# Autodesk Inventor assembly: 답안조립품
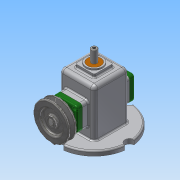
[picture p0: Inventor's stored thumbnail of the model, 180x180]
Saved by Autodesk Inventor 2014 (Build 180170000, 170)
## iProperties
Created: 2018-07
Part Number: 답안조립품
Document SubType Name: Assembly
Designer: user
Author: user
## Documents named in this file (14)
- C:\Users\user\Desktop\480707V1005\답안조립품.iam
- C:\Users\user\Desktop\480707V1005\본체.ipt
- C:\Users\user\Desktop\480707V1005\앞커버.ipt
- C:\Users\user\Desktop\480707V1005\뒤커버.ipt
- C:\Users\user\Desktop\480707V1005\베어링 12x32x10.ipt
- C:\Users\user\Desktop\480707V1005\오일 실 12 25 7.ipt
- C:\Users\user\Desktop\480707V1005\편심축.ipt
- C:\Users\user\Desktop\480707V1005\V벨트풀리.ipt
- C:\Users\user\Desktop\480707V1005\링크.ipt
- C:\Users\user\Desktop\480707V1005\슬라이드.ipt
- C:\Users\user\Desktop\480707V1005\부시.ipt
- C:\Users\user\Desktop\480707V1005\핀 5x18.ipt
- C:\Users\user\Desktop\480707V1005\고정핀 1.2x8.ipt
- C:\Users\user\Desktop\480707V1005\키 4x4x10.ipt
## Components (3 placed, 3 different names)
1. V벨트풀리:1 — 플러쉬:2
2. 핀 5x18:1
3. 고정핀 1.2x8:1
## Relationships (1: Flush 1)
- 플러쉬:2 [Flush]: V벨트풀리:1
